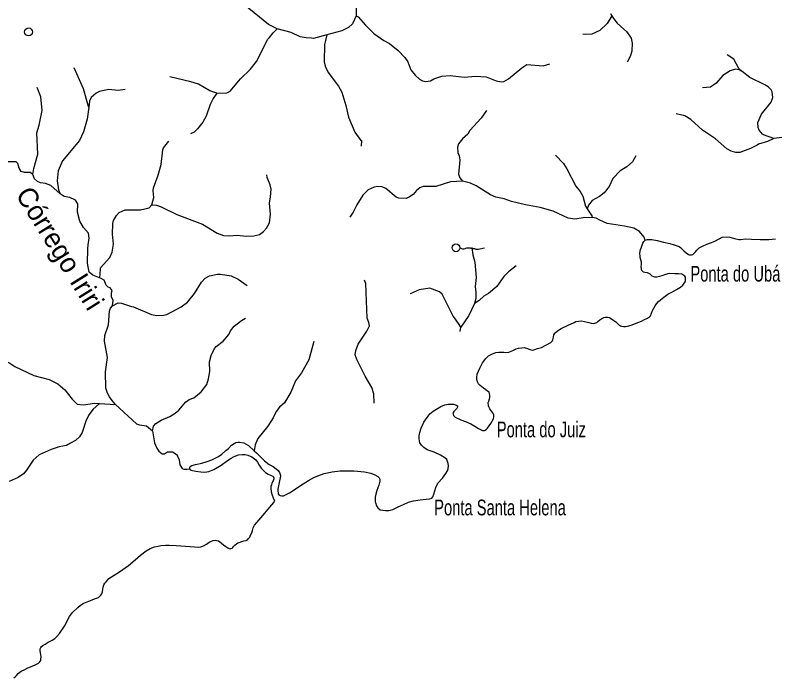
# Model space of a CAD drawing. Extents: x 317.8 to 344.1, y 7676.8 to 7704.8.
# Drawn here: x 321.691 to 325.558, y 7694.355 to 7697.725 of the extents above; entities that cross this region are included whole.
import ezdxf
from ezdxf.enums import TextEntityAlignment as Align

# ---------------------------------------------------------------- set-up
doc = ezdxf.new("R2010")
doc.units = 0
doc.header["$LTSCALE"] = 0.032
for name, color, linetype, lineweight in [('2', 7, 'Continuous', 25), ('22', 7, 'Continuous', 25), ('23', 7, 'Continuous', 25), ('7', 7, 'Continuous', 25)]:
    doc.layers.add(name, color=color, linetype=linetype, lineweight=lineweight)
doc.layers.add('61', color=7, linetype='Continuous')

msp = doc.modelspace()

# ---------------------------------------------------------------- linework, layer by layer
at = {"layer": '2'}
for points in [[(324.8993, 7696.5805), (324.911, 7696.5844), (324.932, 7696.5836), (324.9592, 7696.579), (324.9919, 7696.5712), (325.0238, 7696.5642), (325.0463, 7696.5572), (325.0712, 7696.5479), (325.0782, 7696.544), (325.0961, 7696.5269), (325.107, 7696.516), (325.1194, 7696.5074), (325.1241, 7696.5066), (325.1303, 7696.5066), (325.135, 7696.5066), (325.1412, 7696.5082), (325.1451, 7696.5113), (325.1552, 7696.5214), (325.1614, 7696.5308), (325.1739, 7696.5416), (325.1902, 7696.5502), (325.2128, 7696.5611), (325.2361, 7696.5689), (325.2532, 7696.5751), (325.275, 7696.5875), (325.2913, 7696.5953), (325.31, 7696.5976), (325.3302, 7696.5969), (325.3528, 7696.5891), (325.3746, 7696.5836), (325.3831, 7696.5836), (325.4096, 7696.5875), (325.4391, 7696.586), (325.4842, 7696.5844), (325.5278, 7696.5844), (325.5628, 7696.5868)], [(325.1031, 7696.3721), (325.1039, 7696.3853), (325.1031, 7696.3931), (325.1008, 7696.3977), (325.0852, 7696.4079), (325.0681, 7696.4102), (325.0487, 7696.4102), (325.0207, 7696.411), (325.0028, 7696.4055), (324.9841, 7696.3993), (324.9716, 7696.3954), (324.9576, 7696.3923), (324.9483, 7696.3923), (324.9421, 7696.3946), (324.9343, 7696.3977), (324.9234, 7696.4086), (324.918, 7696.4117), (324.9102, 7696.4149), (324.897, 7696.4164), (324.89, 7696.4187), (324.8861, 7696.4219), (324.8822, 7696.4273), (324.8799, 7696.4327), (324.8791, 7696.4359), (324.8783, 7696.446), (324.8791, 7696.4592), (324.8791, 7696.4685), (324.8768, 7696.4802), (324.8736, 7696.4919), (324.8729, 7696.4981), (324.8721, 7696.5152), (324.8752, 7696.5339), (324.8799, 7696.5455), (324.8869, 7696.565), (324.8923, 7696.5735), (324.8993, 7696.5805)], [(325.0588, 7696.3301), (325.0782, 7696.3417), (325.0907, 7696.3526), (325.0938, 7696.3565), (325.1023, 7696.3697), (325.1031, 7696.3721)], [(324.1005, 7695.7374), (324.0997, 7695.7553), (324.1021, 7695.7623), (324.1059, 7695.7739), (324.1075, 7695.7809), (324.1083, 7695.7903), (324.1067, 7695.8004), (324.1036, 7695.8074), (324.0966, 7695.8136), (324.0881, 7695.8198), (324.0748, 7695.8284), (324.0585, 7695.8416), (324.0507, 7695.8502), (324.0445, 7695.8603), (324.0414, 7695.8719), (324.0414, 7695.8828), (324.0437, 7695.8992), (324.0569, 7695.9303), (324.0709, 7695.9567), (324.0881, 7695.9785), (324.1013, 7695.9925), (324.1175, 7696.0016), (324.1207, 7696.0034), (324.1378, 7696.0096), (324.1542, 7696.0104), (324.1783, 7696.0104), (324.1899, 7696.0096), (324.2047, 7696.0119), (324.2125, 7696.0143), (324.2281, 7696.0213), (324.2413, 7696.0283), (324.2545, 7696.0322), (324.2708, 7696.0337), (324.2825, 7696.0345), (324.2996, 7696.0298), (324.3113, 7696.0244), (324.323, 7696.0221), (324.3315, 7696.0228), (324.351, 7696.0291), (324.3704, 7696.0353), (324.4178, 7696.0602), (324.4248, 7696.0664), (324.4287, 7696.0742), (324.4311, 7696.0882), (324.4334, 7696.0991), (324.4381, 7696.1084), (324.4412, 7696.1115), (324.4567, 7696.1224), (324.4715, 7696.1317), (324.5034, 7696.1465), (324.5369, 7696.1628), (324.5454, 7696.1675), (324.5602, 7696.1683), (324.5742, 7696.1698), (324.5905, 7696.1675), (324.6115, 7696.1613), (324.6232, 7696.1582), (324.6349, 7696.1574), (324.6419, 7696.1582), (324.6527, 7696.1628), (324.6582, 7696.1675), (324.6683, 7696.1753), (324.6776, 7696.1831), (324.6877, 7696.1877), (324.6971, 7696.1885), (324.7072, 7696.1893), (324.715, 7696.187), (324.7227, 7696.1838), (324.7344, 7696.1761), (324.7484, 7696.166), (324.757, 7696.1566), (324.7647, 7696.1504), (324.7671, 7696.1488), (324.7725, 7696.1457), (324.7772, 7696.1434), (324.7881, 7696.1411), (324.799, 7696.1418), (324.8145, 7696.145), (324.8316, 7696.1504), (324.8526, 7696.1582), (324.8791, 7696.1691), (324.8915, 7696.1761), (324.911, 7696.1838), (324.9203, 7696.1901), (324.9258, 7696.1963), (324.9312, 7696.2087), (324.9351, 7696.2227), (324.9491, 7696.2469), (324.9561, 7696.2577), (324.9662, 7696.2686), (324.9763, 7696.278), (324.9934, 7696.2912), (325.0144, 7696.306), (325.0339, 7696.3169), (325.0588, 7696.3301)], [(323.0582, 7695.28), (323.0878, 7695.2964), (323.157, 7695.3415), (323.185, 7695.3577), (323.2122, 7695.3734), (323.2317, 7695.3827), (323.2643, 7695.3936), (323.3056, 7695.4029), (323.346, 7695.4076), (323.416, 7695.4076), (323.4697, 7695.4021), (323.5016, 7695.3951), (323.5226, 7695.3866), (323.5381, 7695.378), (323.5444, 7695.3718), (323.5482, 7695.3648), (323.5482, 7695.3547), (323.542, 7695.3353), (323.5319, 7695.3072), (323.5272, 7695.2894), (323.5241, 7695.2738), (323.5234, 7695.2645), (323.5241, 7695.2505), (323.5249, 7695.2458), (323.5304, 7695.2295), (323.5381, 7695.2201), (323.5498, 7695.2092), (323.5622, 7695.2069), (323.5762, 7695.2054), (323.5934, 7695.2061), (323.6144, 7695.2108), (323.6385, 7695.2232), (323.6711, 7695.2372), (323.6945, 7695.2474), (323.7186, 7695.2551), (323.7536, 7695.2606), (323.7831, 7695.2637), (323.801, 7695.2652), (323.8119, 7695.2691), (323.8174, 7695.2746), (323.8228, 7695.2894), (323.8329, 7695.3236), (323.843, 7695.3446), (323.8672, 7695.371), (323.8843, 7695.3944), (323.8928, 7695.4068), (323.8959, 7695.4185), (323.8975, 7695.4325), (323.8959, 7695.4449), (323.8928, 7695.4558), (323.8882, 7695.4651), (323.878, 7695.4745), (323.857, 7695.4877), (323.8251, 7695.5025), (323.7886, 7695.5141), (323.7715, 7695.5258), (323.7598, 7695.5375), (323.752, 7695.5499), (323.7474, 7695.5709), (323.7474, 7695.5857), (323.752, 7695.6028), (323.7575, 7695.6246), (323.7723, 7695.6549), (323.8026, 7695.6969), (323.8197, 7695.7117), (323.8415, 7695.7249), (323.8586, 7695.735), (323.8788, 7695.7436), (323.8959, 7695.7459), (323.9162, 7695.7467), (323.9232, 7695.7467), (323.9348, 7695.7436), (323.9403, 7695.7405), (323.9434, 7695.7374), (323.9434, 7695.7312), (323.9395, 7695.7249), (323.9333, 7695.7172), (323.9247, 7695.7094), (323.92, 7695.7016), (323.9208, 7695.6954), (323.9224, 7695.6892), (323.9309, 7695.6806), (323.9605, 7695.6674), (323.9838, 7695.658), (324.0103, 7695.6464), (324.032, 7695.6355), (324.0492, 7695.6223), (324.0702, 7695.6129), (324.0803, 7695.6129), (324.0842, 7695.6145), (324.0912, 7695.6192), (324.0951, 7695.6238), (324.1129, 7695.6487), (324.1262, 7695.6728), (324.1277, 7695.6829)], [(324.1277, 7695.6829), (324.1277, 7695.693), (324.1238, 7695.7032), (324.1075, 7695.7226), (324.1021, 7695.7327), (324.1005, 7695.7374)], [(322.5806, 7695.4185), (322.5806, 7695.4247), (322.5822, 7695.4294), (322.59, 7695.4348), (322.6094, 7695.4395), (322.6421, 7695.4473), (322.6693, 7695.455), (322.6926, 7695.4628), (322.7137, 7695.4737), (322.7261, 7695.4807), (322.7432, 7695.4924), (322.7642, 7695.511), (322.7782, 7695.5219), (322.793, 7695.5375), (322.8054, 7695.5468), (322.8155, 7695.5515), (322.8257, 7695.5538), (322.8342, 7695.5538), (322.8552, 7695.5507), (322.8785, 7695.5367), (322.9087, 7695.5089)], [(322.9087, 7695.5089), (322.9198, 7695.4986), (322.9602, 7695.4589), (322.9843, 7695.4403), (323.0053, 7695.4294), (323.0201, 7695.4169), (323.0302, 7695.4091), (323.0372, 7695.399), (323.0411, 7695.3897), (323.0419, 7695.3796), (323.0352, 7695.3484), (323.0279, 7695.3142), (323.0279, 7695.3034), (323.0294, 7695.2932), (323.031, 7695.2901), (323.0341, 7695.2855), (323.0403, 7695.2824), (323.0489, 7695.2808), (323.0582, 7695.28)], [(322.5806, 7695.4185), (322.5822, 7695.4138), (322.5869, 7695.4115), (322.5939, 7695.4084), (322.611, 7695.4053), (322.6359, 7695.4029), (322.6576, 7695.4006), (322.6779, 7695.4037), (322.7028, 7695.4138), (322.7401, 7695.4371), (322.7728, 7695.4605), (322.7914, 7695.4721), (322.8054, 7695.4807), (322.8288, 7695.4885), (322.8467, 7695.4908), (322.8614, 7695.49), (322.8762, 7695.4869), (322.8957, 7695.4784), (322.9167, 7695.4636), (322.9252, 7695.4511), (322.933, 7695.4371), (322.9431, 7695.4216), (322.9532, 7695.4107), (322.9664, 7695.399), (322.9797, 7695.3905), (322.9944, 7695.3843), (323.003, 7695.3811), (323.0053, 7695.3773), (323.0084, 7695.3726), (323.0077, 7695.3664), (323.0046, 7695.3563), (323.0014, 7695.3508), (322.9983, 7695.3438), (322.996, 7695.336), (322.9937, 7695.3283), (322.9929, 7695.3189), (322.9952, 7695.301), (322.9999, 7695.2831), (323.0053, 7695.2699), (323.0113, 7695.2544)], [(322.7739, 7695.0154), (322.7811, 7695.0118), (322.7863, 7695.0108), (322.7899, 7695.0118), (322.7956, 7695.0144), (322.7987, 7695.0175), (322.8028, 7695.0226), (322.809, 7695.0293), (322.8173, 7695.036), (322.8245, 7695.0407), (322.8312, 7695.0438), (322.8451, 7695.0484), (322.856, 7695.0515), (322.8668, 7695.0536), (322.8735, 7695.0572), (322.8792, 7695.0629), (322.8854, 7695.0696), (322.89, 7695.0799), (322.8957, 7695.0918), (322.8988, 7695.1042), (322.9024, 7695.1171), (322.9055, 7695.1248), (322.9097, 7695.1315), (322.922, 7695.1444), (322.9628, 7695.1924), (322.9886, 7695.2229), (323.0082, 7695.2461), (323.0113, 7695.2544)], [(321.6844, 7694.3548), (321.6916, 7694.3605), (321.6978, 7694.3667), (321.7071, 7694.377), (321.7149, 7694.3827), (321.7226, 7694.3883), (321.7407, 7694.3971), (321.7562, 7694.4048), (321.7783, 7694.4146), (321.7974, 7694.4229), (321.8093, 7694.4291), (321.8176, 7694.4368), (321.8212, 7694.4425), (321.8227, 7694.4497), (321.8232, 7694.4621), (321.8227, 7694.4714), (321.8191, 7694.4936), (321.8191, 7694.5014), (321.8222, 7694.5086), (321.8258, 7694.5132), (321.832, 7694.5189), (321.8434, 7694.5266), (321.8599, 7694.5354), (321.88, 7694.5468), (321.8934, 7694.555), (321.9038, 7694.5643), (321.9172, 7694.5793), (321.942, 7694.6175), (321.9678, 7694.666), (321.9827, 7694.6866), (322.0106, 7694.7124), (322.0235, 7694.7238), (322.0369, 7694.7326), (322.0534, 7694.7398), (322.071, 7694.7465), (322.0859, 7694.7532), (322.1009, 7694.7584), (322.1148, 7694.7635), (322.1231, 7694.7702), (322.1272, 7694.7754), (322.1319, 7694.7821), (322.1355, 7694.7924), (322.137, 7694.8059), (322.1386, 7694.8157), (322.1432, 7694.8275), (322.1484, 7694.8363), (322.1551, 7694.8435), (322.1623, 7694.8539), (322.1685, 7694.8595), (322.2222, 7694.8941), (322.2681, 7694.9261), (322.3022, 7694.9545), (322.329, 7694.9788), (322.3574, 7695.0004), (322.3786, 7695.0128), (322.4008, 7695.0206), (322.4188, 7695.0242), (322.4323, 7695.0273), (322.4575, 7695.0288), (322.4756, 7695.0298), (322.5112, 7695.0283), (322.5824, 7695.0221), (322.6258, 7695.0195), (322.6371, 7695.0211), (322.6506, 7695.0262), (322.665, 7695.035), (322.679, 7695.0448), (322.6903, 7695.0505), (322.6996, 7695.0536), (322.7089, 7695.0541), (322.7161, 7695.0536), (322.7264, 7695.0515)], [(322.7264, 7695.0515), (322.7337, 7695.0469), (322.7419, 7695.0397), (322.7512, 7695.0319), (322.7636, 7695.0221), (322.7739, 7695.0154)]]:
    msp.add_lwpolyline(points, dxfattribs=at)
at = {"layer": '22'}
msp.add_circle((323.9353, 7696.5421), 0.02, dxfattribs=at)
msp.add_spline([(323.9553, 7696.5421), (323.9728, 7696.5366), (323.9903, 7696.5411), (324.0068, 7696.5411), (324.0138, 7696.5406), (324.0218, 7696.5391), (324.0293, 7696.5381), (324.0368, 7696.5356), (324.0498, 7696.5356), (324.0803, 7696.5421)], degree=3, dxfattribs=at)
at = {"layer": '23'}
msp.add_circle((321.7594, 7697.6402), 0.02, dxfattribs=at)
at = {"layer": '7'}
msp.add_line((323.9567, 7696.1155), (323.9598, 7696.1381), dxfattribs=at)
for points in [[(323.4513, 7698.1901), (323.4421, 7698.1766), (323.431, 7698.1455), (323.4306, 7698.118), (323.4142, 7698.0144), (323.4175, 7697.8729), (323.4272, 7697.8038), (323.428, 7697.7222)], [(323.0254, 7697.655), (322.9806, 7697.6776), (322.835, 7697.7963), (322.7864, 7697.8269), (322.7395, 7697.8443), (322.6784, 7697.859), (322.5771, 7697.9071), (322.5336, 7697.9166)], [(323.428, 7697.7222), (323.4084, 7697.6807), (323.3878, 7697.6619), (323.3548, 7697.6455), (323.2784, 7697.6253)], [(323.428, 7697.7222), (323.4368, 7697.7162), (323.4742, 7697.6737), (323.5172, 7697.6325), (323.5687, 7697.5968), (323.597, 7697.581), (323.6413, 7697.5459), (323.6754, 7697.5103), (323.6898, 7697.4882), (323.7064, 7697.4471), (323.7272, 7697.4208), (323.75, 7697.4004), (323.7653, 7697.3919), (323.7812, 7697.3876), (323.8057, 7697.3916), (323.8228, 7697.4009), (323.8629, 7697.4152), (323.9059, 7697.4192), (323.9777, 7697.4095), (324.0346, 7697.4159), (324.0893, 7697.4109), (324.1401, 7697.3918), (324.1673, 7697.3866), (324.1797, 7697.3887), (324.2034, 7697.4016), (324.2703, 7697.4581), (324.2968, 7697.4745), (324.3786, 7697.4673), (324.4135, 7697.4772)], [(324.7288, 7697.7219), (324.7046, 7697.683), (324.6674, 7697.6478), (324.627, 7697.6279), (324.5941, 7697.6263), (324.5806, 7697.6287)], [(324.7221, 7697.7344), (324.7288, 7697.7219)], [(324.7288, 7697.7219), (324.7365, 7697.7076), (324.7564, 7697.6843), (324.7723, 7697.6702), (324.8052, 7697.641), (324.8276, 7697.609), (324.8323, 7697.5821), (324.8307, 7697.542), (324.8227, 7697.5148), (324.8064, 7697.4861)], [(322.7183, 7697.328), (322.7684, 7697.3303), (322.786, 7697.3381), (322.8385, 7697.401), (322.8869, 7697.4484), (322.9191, 7697.4895), (322.9784, 7697.6032), (322.9857, 7697.6122), (323.005, 7697.6357), (323.0254, 7697.655)], [(323.2784, 7697.6253), (323.2108, 7697.6075), (323.2004, 7697.608), (323.1725, 7697.6092), (323.142, 7697.6157), (323.0967, 7697.6367), (323.0254, 7697.655)], [(323.2784, 7697.6253), (323.271, 7697.5962), (323.2659, 7697.5761), (323.2643, 7697.4882), (323.2697, 7697.4664), (323.2854, 7697.433), (323.3374, 7697.3649), (323.3538, 7697.3339), (323.3747, 7697.2651), (323.3875, 7697.207), (323.4209, 7697.1294), (323.4504, 7697.0883), (323.4541, 7697.087), (323.4534, 7697.059)], [(325.3924, 7697.4394), (325.3761, 7697.4542), (325.3493, 7697.502), (325.3157, 7697.5236)], [(322.0656, 7697.257), (322.0645, 7697.2608), (322.0392, 7697.3502), (321.9921, 7697.4568)], [(325.3924, 7697.4394), (325.3768, 7697.4474), (325.3585, 7697.4501), (325.3308, 7697.4427), (325.2931, 7697.4186), (325.2599, 7697.3789), (325.2314, 7697.359), (325.1902, 7697.3549)], [(325.5534, 7697.0978), (325.5012, 7697.117), (325.4953, 7697.1192), (325.4783, 7697.1407), (325.4736, 7697.1539), (325.4723, 7697.1795), (325.4899, 7697.2225), (325.5396, 7697.2832), (325.5486, 7697.3072), (325.545, 7697.3362), (325.5406, 7697.3448), (325.5251, 7697.3605), (325.5085, 7697.3713), (325.4316, 7697.4082), (325.3924, 7697.4394)], [(322.7183, 7697.328), (322.6827, 7697.3408), (322.6244, 7697.3741), (322.5856, 7697.3867), (322.4779, 7697.412)], [(321.7805, 7696.9153), (321.7859, 7696.9461), (321.8061, 7697.0176), (321.8013, 7697.1261), (321.8136, 7697.1664), (321.8282, 7697.2407), (321.8217, 7697.3092), (321.8039, 7697.3573)], [(322.2513, 7697.3468), (322.2156, 7697.3426), (322.1683, 7697.3467), (322.1207, 7697.3371), (322.104, 7697.3289), (322.0786, 7697.307), (322.0694, 7697.2876), (322.0656, 7697.257)], [(322.7183, 7697.328), (322.6988, 7697.3013), (322.684, 7697.2717), (322.6629, 7697.2109), (322.6474, 7697.1816), (322.6204, 7697.1478), (322.6018, 7697.1302), (322.5838, 7697.121)], [(322.0656, 7697.257), (322.0581, 7697.1971), (322.04, 7697.1312), (322.0181, 7697.088), (321.9322, 7696.9838), (321.9098, 7696.9331), (321.9056, 7696.8822), (321.9127, 7696.8377), (321.921, 7696.8165)], [(324.0916, 7697.24), (324.0642, 7697.2013), (324.0064, 7697.1386), (323.9954, 7697.1202), (323.9679, 7697.0967), (323.9484, 7697.0717), (323.9432, 7697.0532), (323.944, 7697.0275), (323.9517, 7697.0092), (323.9545, 7696.989), (323.9481, 7696.9164), (323.9556, 7696.898), (323.9694, 7696.8805)], [(325.5534, 7697.0978), (325.5215, 7697.0833), (325.4751, 7697.0684), (325.468, 7697.0645), (325.4351, 7697.0466), (325.38, 7697.0264), (325.3602, 7697.0272), (325.3364, 7697.0333), (325.3144, 7697.0459), (325.2572, 7697.0964), (325.1903, 7697.1412), (325.1318, 7697.1946), (325.1007, 7697.2127), (325.0566, 7697.2237)], [(325.6413, 7696.8411), (325.6499, 7696.8746), (325.6534, 7696.9185), (325.6612, 7696.9503), (325.7031, 7697.0456), (325.7117, 7697.081), (325.7125, 7697.1131), (325.7051, 7697.1248), (325.6904, 7697.1305), (325.6718, 7697.1306), (325.5949, 7697.1037), (325.5534, 7697.0978)], [(322.3879, 7696.761), (322.397, 7696.7973), (322.3931, 7696.8321), (322.3948, 7696.8466), (322.42, 7696.9117), (322.4339, 7696.9659), (322.4425, 7697.0395), (322.4473, 7697.0507), (322.473, 7697.0851)], [(324.4412, 7697.0134), (324.4822, 7696.9706), (324.5002, 7696.9445), (324.5453, 7696.8548), (324.568, 7696.8286), (324.5809, 7696.8048), (324.5945, 7696.7536), (324.6035, 7696.7401)], [(324.8512, 7697.0101), (324.8346, 7696.9789), (324.8057, 7696.9543), (324.7714, 7696.9341), (324.7347, 7696.8937), (324.7153, 7696.8538), (324.69, 7696.8221), (324.6666, 7696.8037), (324.628, 7696.7821), (324.6107, 7696.7582), (324.6035, 7696.7401)], [(321.7805, 7696.9153), (321.7676, 7696.9253), (321.7383, 7696.9258), (321.7226, 7696.9301), (321.7122, 7696.9477), (321.7043, 7696.9708), (321.697, 7696.9789), (321.6484, 7696.9792)], [(321.921, 7696.8165), (321.8722, 7696.8593), (321.8465, 7696.8697), (321.8209, 7696.873), (321.8053, 7696.8794), (321.7895, 7696.8925), (321.7805, 7696.9153)], [(322.3879, 7696.761), (322.4107, 7696.7581), (322.4344, 7696.7509), (322.5147, 7696.7116), (322.6456, 7696.6628), (322.7191, 7696.6167), (322.7526, 7696.6053), (322.7804, 7696.6025), (322.8207, 7696.6059), (322.8692, 7696.6018), (322.9056, 7696.6034), (322.9355, 7696.6099), (322.956, 7696.6251), (322.9712, 7696.6413), (322.9856, 7696.6689), (322.9905, 7696.7124), (322.9864, 7696.769), (322.992, 7696.8007), (322.9944, 7696.8397), (322.9901, 7696.8619), (322.9741, 7696.9004), (322.9726, 7696.914)], [(323.9694, 7696.8805), (323.9078, 7696.8772), (323.8336, 7696.8535), (323.7689, 7696.8533), (323.752, 7696.8479), (323.7348, 7696.8342), (323.7176, 7696.8132), (323.6991, 7696.8005), (323.6817, 7696.7932), (323.6453, 7696.7946), (323.6316, 7696.8004), (323.578, 7696.8436), (323.5601, 7696.8517), (323.5374, 7696.8543), (323.5192, 7696.8506), (323.4881, 7696.8364), (323.4604, 7696.81), (323.4307, 7696.7601), (323.4128, 7696.7228), (323.3956, 7696.6972)], [(324.6295, 7696.6963), (324.5832, 7696.6948), (324.5401, 7696.6882), (324.507, 7696.692), (324.4294, 7696.7289), (324.3645, 7696.7468), (324.2888, 7696.76), (324.2184, 7696.7774), (324.18, 7696.7909), (324.1387, 7696.7995), (324.1113, 7696.8108), (324.0385, 7696.8576), (324.01, 7696.8715), (323.9694, 7696.8805)], [(322.1207, 7696.3901), (322.0868, 7696.402), (322.0686, 7696.4179), (322.0589, 7696.4645), (322.0621, 7696.5372), (322.063, 7696.5565), (322.0679, 7696.5916), (322.0646, 7696.6173), (322.0388, 7696.6455), (322.0197, 7696.6771), (322.008, 7696.7229), (322.0108, 7696.7651), (321.9981, 7696.7846), (321.9692, 7696.7981), (321.9408, 7696.803), (321.921, 7696.8165)], [(322.1207, 7696.3901), (322.1248, 7696.403), (322.1266, 7696.4403), (322.1725, 7696.4919), (322.1852, 7696.519), (322.1918, 7696.5611), (322.1869, 7696.6108), (322.1885, 7696.6659), (322.1919, 7696.6815), (322.207, 7696.7057), (322.2213, 7696.7209), (322.2511, 7696.7344), (322.3286, 7696.7346), (322.3731, 7696.746), (322.3879, 7696.761)], [(324.6035, 7696.7401), (324.6275, 7696.7043), (324.6295, 7696.6963)], [(324.8993, 7696.5805), (324.8934, 7696.5959), (324.8698, 7696.6253), (324.8415, 7696.6426), (324.7939, 7696.6529), (324.7055, 7696.6653), (324.6672, 7696.6833), (324.6488, 7696.692), (324.6295, 7696.6963)], [(324.0158, 7696.544), (324.0206, 7696.506), (324.0311, 7696.4681), (324.0385, 7696.3905), (324.0337, 7696.3454), (324.0369, 7696.3159), (324.0361, 7696.2846), (324.0293, 7696.2584)], [(324.2415, 7696.4502), (324.202, 7696.4202), (324.1785, 7696.3962), (324.1438, 7696.3453), (324.1017, 7696.3103), (324.0774, 7696.2967), (324.054, 7696.2742), (324.0293, 7696.2584)], [(322.1861, 7696.246), (322.2165, 7696.2618), (322.2321, 7696.2603), (322.2831, 7696.2432), (322.2938, 7696.2422), (322.3857, 7696.2025), (322.4131, 7696.1984), (322.4457, 7696.1991), (322.4629, 7696.2026), (322.5359, 7696.2417), (322.5688, 7696.2656), (322.6041, 7696.3101), (322.6396, 7696.3667), (322.6588, 7696.3872), (322.6804, 7696.3995), (322.7213, 7696.4085), (322.7369, 7696.4086), (322.7909, 7696.3989), (322.8273, 7696.3829), (322.8723, 7696.35)], [(322.1861, 7696.246), (322.1899, 7696.276), (322.182, 7696.2916), (322.182, 7696.3136), (322.1852, 7696.3243), (322.1753, 7696.3376), (322.1652, 7696.3416), (322.1549, 7696.3512), (322.1445, 7696.3782), (322.1266, 7696.388), (322.1207, 7696.3901)], [(323.5186, 7695.7518), (323.517, 7695.7991), (323.5074, 7695.8317), (323.4739, 7695.889), (323.4307, 7695.9739), (323.4224, 7695.9971), (323.4248, 7696.0195), (323.4369, 7696.0521), (323.4814, 7696.1183), (323.4957, 7696.1449), (323.4923, 7696.1619), (323.4825, 7696.184), (323.4769, 7696.3597), (323.4697, 7696.3777)], [(323.9598, 7696.1381), (323.949, 7696.1576), (323.9281, 7696.1853), (323.9215, 7696.194), (323.8653, 7696.3064), (323.8521, 7696.3182), (323.8021, 7696.336), (323.7485, 7696.3287), (323.702, 7696.3076)], [(322.2015, 7695.7455), (322.1856, 7695.7655), (322.171, 7695.7838), (322.1612, 7695.8022), (322.1535, 7695.8288), (322.1517, 7695.9119), (322.1607, 7695.9844), (322.1469, 7696.0671), (322.1486, 7696.0952), (322.1665, 7696.1506), (322.1722, 7696.219), (322.1767, 7696.2351), (322.1861, 7696.246)], [(324.0293, 7696.2584), (324.0004, 7696.1979), (323.9598, 7696.1381)], [(322.39, 7695.6116), (322.3958, 7695.6344), (322.4067, 7695.6488), (322.4343, 7695.6659), (322.4779, 7695.6836), (322.5054, 7695.7004), (322.5237, 7695.7162), (322.5606, 7695.7577), (322.5688, 7695.7634), (322.5776, 7695.7696), (322.6005, 7695.7789), (322.6389, 7695.8086), (322.6665, 7695.8475), (322.6757, 7695.8753), (322.6824, 7695.9131), (322.6814, 7695.9613), (322.6891, 7695.9943), (322.7053, 7696.029), (322.7154, 7696.0405), (322.751, 7696.0674), (322.7783, 7696.1011), (322.7874, 7696.119), (322.8061, 7696.1427), (322.8435, 7696.172), (322.8642, 7696.1837)], [(323.2122, 7696.0647), (323.1863, 7695.9716), (323.1483, 7695.9054), (323.1181, 7695.8646), (323.0946, 7695.8076), (323.0625, 7695.753), (323.0363, 7695.7308), (323.0194, 7695.7091), (323.0042, 7695.6775), (322.9776, 7695.6351), (322.9267, 7695.572), (322.9163, 7695.5486), (322.9124, 7695.5397), (322.9087, 7695.5089)], [(321.4057, 7696.0271), (321.449, 7696.0262), (321.4926, 7696.0138), (321.6044, 7695.9819), (321.6649, 7695.9548), (321.6901, 7695.9382), (321.7861, 7695.8918), (321.8644, 7695.8722), (321.9087, 7695.8508), (321.9445, 7695.8196), (321.9807, 7695.7714), (322.0064, 7695.7469), (322.0396, 7695.7436), (322.096, 7695.7516), (322.1208, 7695.7502)], [(322.1208, 7695.7502), (322.087, 7695.7196), (322.0678, 7695.6938), (322.0521, 7695.6655), (322.0317, 7695.6019), (322.0187, 7695.5811), (321.999, 7695.5622), (321.9737, 7695.5479), (321.9531, 7695.5363), (321.9147, 7695.5295), (321.8752, 7695.5168), (321.8128, 7695.4884), (321.7827, 7695.4614), (321.7494, 7695.4114), (321.7331, 7695.3925), (321.7063, 7695.3729), (321.6614, 7695.3533)], [(322.1208, 7695.7502), (322.1756, 7695.747), (322.2015, 7695.7455)], [(322.2015, 7695.7455), (322.3083, 7695.6463), (322.3251, 7695.6409), (322.3594, 7695.6368), (322.39, 7695.6116)], [(322.39, 7695.6116), (322.4003, 7695.5503), (322.4004, 7695.5502), (322.4119, 7695.5223), (322.4219, 7695.5077), (322.4404, 7695.4934), (322.4519, 7695.494), (322.4667, 7695.5036), (322.4919, 7695.5044), (322.5106, 7695.4921), (322.5125, 7695.4909), (322.5178, 7695.4824), (322.5258, 7695.463), (322.5292, 7695.438), (322.5407, 7695.4193), (322.5503, 7695.4159), (322.5675, 7695.4168), (322.5806, 7695.4185)]]:
    msp.add_lwpolyline(points, dxfattribs=at)

# ---------------------------------------------------------------- texts
at = {"layer": '61'}
msp.add_text('Córrego Iriri', height=0.1, rotation=301.957, dxfattribs=at).set_placement((321.8772, 7696.5133), align=Align.CENTER)
at = {"layer": '61', "width": 0.7}
for s, p in [('Ponta do Ubá', (325.1287, 7696.3702)), ('Ponta do Juiz', (324.1431, 7695.5781)), ('Ponta Santa Helena', (323.8245, 7695.1811))]:
    msp.add_text(s, height=0.08, dxfattribs=at).set_placement(p)

doc.saveas('drawing.dxf')
